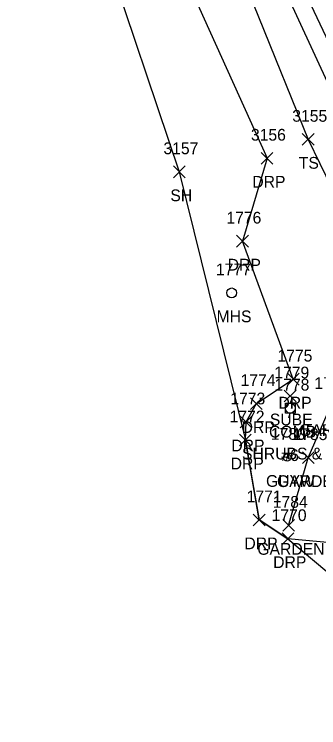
# Model space of a CAD drawing. Extents: x 1462668 to 1465147, y 550359 to 557351.
# Drawn here: x 1464530.7 to 1464582.5, y 552731.2 to 552852.6 of the extents above; entities that cross this region are included whole.
import ezdxf

# ---------------------------------------------------------------- set-up
doc = ezdxf.new("R2010")
doc.units = 0
for name, color, linetype in [('L_A', 7, 'Continuous'), ('L_C', 7, 'Continuous'), ('L_I', 7, 'Continuous'), ('L_TIC', 7, 'Continuous'), ('LAPB', 7, 'Continuous'), ('LELB', 7, 'Continuous'), ('Level 6', 7, 'Continuous'), ('R_A', 7, 'Continuous'), ('R_I', 7, 'Continuous'), ('R_TIC', 7, 'Continuous'), ('RDP', 7, 'Continuous'), ('RRB', 7, 'Continuous'), ('U_A', 7, 'Continuous'), ('U_C', 7, 'Continuous'), ('U_I', 7, 'Continuous'), ('U_TIC', 7, 'Continuous'), ('UP', 7, 'Continuous'), ('UPGW', 7, 'Continuous'), ('USMH', 7, 'Continuous')]:
    doc.layers.add(name, color=color, linetype=linetype)

msp = doc.modelspace()

# ---------------------------------------------------------------- linework, layer by layer
at = {"layer": 'L_TIC'}
for points in [[(1464579.7, 552830.35), (1464581.7, 552832.35)], [(1464581.7, 552830.35), (1464579.7, 552832.35)], [(1464557.75, 552824.82), (1464559.75, 552826.82)], [(1464559.75, 552824.82), (1464557.75, 552826.82)], [(1464579.73, 552776.15), (1464581.73, 552778.15)], [(1464581.73, 552776.15), (1464579.73, 552778.15)], [(1464576.38, 552764.62), (1464578.38, 552766.62)], [(1464578.38, 552764.62), (1464576.38, 552766.62)]]:
    msp.add_lwpolyline(points, dxfattribs=at)
at = {"layer": 'LAPB'}
msp.add_lwpolyline([(1464577.38, 552765.62), (1464580.73, 552777.15), (1464584.5, 552785.85), (1464591.39, 552795.05), (1464598.32, 552781.79)], dxfattribs=at)
at = {"layer": 'LELB'}
for points in [[(1464320.57, 553552.86), (1464335.76, 553496.58), (1464351.01, 553439.58), (1464352, 553433.56), (1464356.91, 553435.89), (1464366.09, 553404.9), (1464375.79, 553365.63), (1464378.91, 553354.3), (1464392.5, 553314.3), (1464410.74, 553264.08), (1464424.65, 553220.18), (1464446.71, 553164.77), (1464462.56, 553121.26), (1464478.7, 553079.34), (1464487.04, 553051.03), (1464509.44, 553004.95), (1464519.17, 552979.76), (1464533.37, 552948.39), (1464548.85, 552915.73), (1464568.29, 552875.06), (1464587.07, 552834.38)], [(1464544.1, 552913.88), (1464563.82, 552873.14), (1464580.7, 552831.35)], [(1464580.7, 552831.35), (1464586.68, 552819.05)]]:
    msp.add_lwpolyline(points, dxfattribs=at)
at = {"layer": 'Level 6'}
msp.add_lwpolyline([(1464545.72, 552864.48), (1464558.75, 552825.82), (1464570.02, 552780.16), (1464571.19, 552773.36), (1464572.36, 552766.56), (1464577.26, 552763.36), (1464590.86, 552751.94), (1464606.28, 552739.27), (1464615.12, 552732.19), (1464637.45, 552714.01)], dxfattribs=at)
at = {"layer": 'R_TIC'}
for points in [[(1464572.71, 552827.13), (1464574.71, 552829.13)], [(1464574.71, 552827.13), (1464572.71, 552829.13)], [(1464568.52, 552813.01), (1464570.52, 552815.01)], [(1464570.52, 552813.01), (1464568.52, 552815.01)], [(1464577.17, 552789.52), (1464579.17, 552791.52)], [(1464579.17, 552789.52), (1464577.17, 552791.52)], [(1464570.89, 552785.35), (1464572.89, 552787.35)], [(1464572.89, 552785.35), (1464570.89, 552787.35)], [(1464569.14, 552782.23), (1464571.14, 552784.23)], [(1464571.14, 552782.23), (1464569.14, 552784.23)], [(1464569.02, 552779.16), (1464571.02, 552781.16)], [(1464571.02, 552779.16), (1464569.02, 552781.16)], [(1464571.36, 552765.56), (1464573.36, 552767.56)], [(1464573.36, 552765.56), (1464571.36, 552767.56)], [(1464576.26, 552762.36), (1464578.26, 552764.36)], [(1464578.26, 552762.36), (1464576.26, 552764.36)]]:
    msp.add_lwpolyline(points, dxfattribs=at)
at = {"layer": 'RDP'}
for points in [[(1464482.22, 552988.94), (1464488.49, 552990.3), (1464492.15, 552982.03), (1464503.51, 552985), (1464507.32, 552975.03), (1464523.33, 552944.39), (1464537.72, 552910.89), (1464555.25, 552869.11), (1464573.71, 552828.13)], [(1464573.71, 552828.13), (1464569.52, 552814.01)], [(1464597.72, 552747.05), (1464599.62, 552749.61), (1464608.93, 552742.74), (1464616.86, 552750.92), (1464599.67, 552779.84), (1464587.7, 552765.56), (1464585.17, 552762.57), (1464577.26, 552763.36), (1464572.36, 552766.56), (1464570.02, 552780.16), (1464570.14, 552783.23), (1464571.89, 552786.35), (1464578.17, 552790.52), (1464569.52, 552814.01)]]:
    msp.add_lwpolyline(points, dxfattribs=at)
at = {"layer": 'RRB'}
msp.add_lwpolyline([(1464320.57, 553552.86), (1464339.05, 553497.3), (1464359.1, 553436.85), (1464368.45, 553406.11), (1464384.33, 553354.99), (1464397.56, 553315.41), (1464413.05, 553265.37), (1464427.98, 553221.45), (1464449.13, 553165.59), (1464464.66, 553122.35), (1464481.22, 553080.02), (1464490.89, 553052.76), (1464510.86, 553007.55), (1464522.32, 552980.59), (1464536.19, 552949.72), (1464551.43, 552916.63), (1464570.99, 552875.75), (1464590.29, 552834.94)], dxfattribs=at)
at = {"layer": 'U_TIC'}
for points in [[(1464576.64, 552786.65), (1464578.64, 552788.65)], [(1464578.64, 552786.65), (1464576.64, 552788.65)]]:
    msp.add_lwpolyline(points, dxfattribs=at)
at = {"layer": 'UP'}
for p, q in [((1464577.9, 552787.25), (1464577.65, 552786.41)), ((1464576.82, 552784.75), (1464576.82, 552786.41)), ((1464576.82, 552786.41), (1464578.49, 552786.41)), ((1464578.49, 552786.41), (1464578.49, 552784.75)), ((1464578.49, 552784.75), (1464576.82, 552784.75)), ((1464577.4, 552783.91), (1464577.65, 552784.75)), ((1464577.65, 552785.58), (1464577.65, 552785.58))]:
    msp.add_line(p, q, dxfattribs=at)
msp.add_circle((1464577.65, 552785.58), 0.833, dxfattribs=at)
at = {"layer": 'UPGW'}
for radius in [0.625, 0.0833]:
    msp.add_circle((1464577.13, 552777.19), radius, dxfattribs=at)
at = {"layer": 'USMH'}
for p, q in [((1464567.69, 552805.21), (1464567.69, 552805.21)), ((1464568.53, 552805.21), (1464568.53, 552805.21))]:
    msp.add_line(p, q, dxfattribs=at)
msp.add_circle((1464567.69, 552805.21), 0.833, dxfattribs=at)

# ---------------------------------------------------------------- texts
at = {"layer": 'L_A'}
for s, p in [('TS', (1464579.11, 552826.35)), ('SH', (1464557.24, 552820.82)), ('GARDEN', (1464579.17, 552780.85)), ('GARDEN', (1464575.4, 552772.15)), ('GARDEN', (1464572.05, 552760.62))]:
    msp.add_text(s, height=2, dxfattribs=at).set_placement(p)
at = {"layer": 'L_C'}
msp.add_text('SHRUBS & FLOWERS', height=2, dxfattribs=at).set_placement((1464569.44, 552776.85))
at = {"layer": 'L_I'}
for s, p in [('3155', (1464578, 552834.35)), ('3157', (1464556.06, 552828.82)), ('1786', (1464581.75, 552788.85)), ('1785', (1464578.04, 552780.15)), ('1784', (1464574.68, 552768.62))]:
    msp.add_text(s, height=2, dxfattribs=at).set_placement(p)
at = {"layer": 'R_A'}
for p in [(1464571.2, 552823.13), (1464567.01, 552809.01), (1464575.65, 552785.52), (1464569.38, 552781.35), (1464567.63, 552778.23), (1464567.51, 552775.16), (1464569.85, 552761.56), (1464574.75, 552758.36)]:
    msp.add_text('DRP', height=2, dxfattribs=at).set_placement(p)
at = {"layer": 'R_I'}
for s, p in [('3156', (1464570.96, 552831.13)), ('1776', (1464566.78, 552817.01)), ('1775', (1464575.47, 552793.52)), ('1774', (1464569.2, 552789.35)), ('1773', (1464567.45, 552786.23)), ('1772', (1464567.33, 552783.16)), ('1771', (1464570.23, 552769.56)), ('1770', (1464574.48, 552766.36))]:
    msp.add_text(s, height=2, dxfattribs=at).set_placement(p)
at = {"layer": 'U_A'}
for s, p in [('MHS', (1464565.11, 552800.21)), ('SUBE', (1464574.18, 552782.65)), ('COMB', (1464574.04, 552780.58)), ('GUYW', (1464573.53, 552772.19))]:
    msp.add_text(s, height=2, dxfattribs=at).set_placement(p)
at = {"layer": 'U_C'}
msp.add_text('#6', height=2, dxfattribs=at).set_placement((1464576.13, 552776.58))
at = {"layer": 'U_I'}
for s, p in [('1777', (1464565, 552808.21)), ('1779', (1464574.94, 552790.65)), ('1778', (1464574.96, 552788.58)), ('1780', (1464574.35, 552780.19))]:
    msp.add_text(s, height=2, dxfattribs=at).set_placement(p)

doc.saveas('drawing.dxf')
